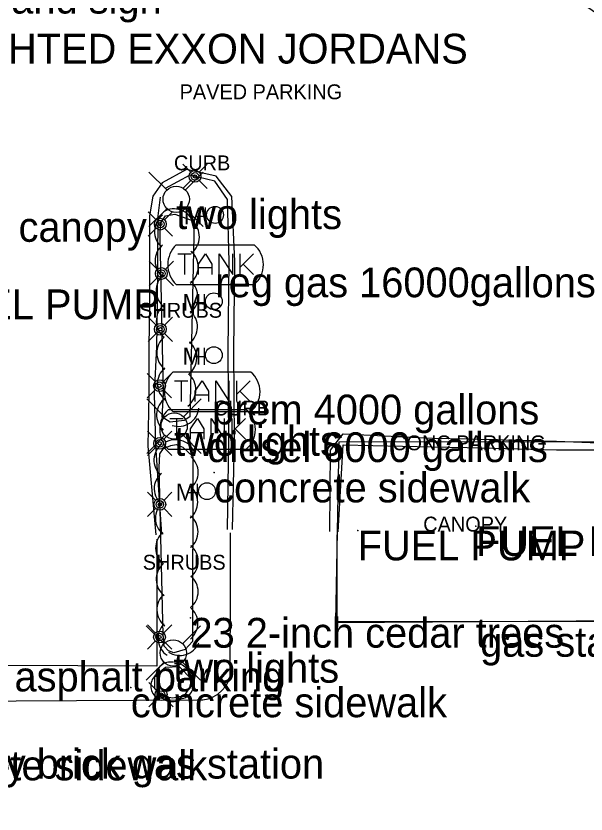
# Model space of a CAD drawing. Extents: x 1802180 to 1804859, y 572524 to 575172.
# Drawn here: x 1803809.7 to 1803905.5, y 573582.9 to 573717 of the extents above; entities that cross this region are included whole.
import ezdxf

# ---------------------------------------------------------------- set-up
doc = ezdxf.new("R2010")
doc.units = 0
for name, color, linetype in [('S_CURB', 7, 'Continuous'), ('S_CURB_ANNOT', 7, 'Continuous'), ('S_MANHOLE', 7, 'Continuous'), ('S_MISC_STRUCTURES', 7, 'Continuous'), ('S_MISC_STRUCTURES_ANNOT', 7, 'Continuous'), ('S_MSC_PT_SYM', 7, 'Continuous'), ('S_PARKING', 7, 'Continuous'), ('S_PARKING_ANNOT', 7, 'Continuous'), ('S_SIGN_ANNOT', 7, 'Continuous'), ('S_SPRINKLER_HEAD', 7, 'Continuous'), ('S_SURVEY_TEXT_ANNOT', 7, 'Continuous'), ('S_TANK', 7, 'Continuous'), ('S_TANK_ANNOT', 7, 'Continuous'), ('S_TREE', 7, 'Continuous'), ('S_TREE_ANNOT', 7, 'Continuous'), ('S_UTILITY_POLE', 7, 'Continuous'), ('S_UTILITY_POLE_ANNOT', 7, 'Continuous')]:
    doc.layers.add(name, color=color, linetype=linetype)

msp = doc.modelspace()

# ---------------------------------------------------------------- linework, layer by layer
at = {"layer": 'S_CURB'}
for points in [[(1803863.81, 573630.28), (1803864.63, 573644.9), (1803879.62, 573644.57), (1803885.5, 573644.45), (1803900.5, 573644.06), (1803911.39, 573644.06), (1803911.79, 573650.56), (1803912.2, 573665.52), (1803912.27, 573667.76), (1803912.6, 573680.35), (1803912.65, 573688), (1803912.94, 573697.46), (1803912.56, 573710.79), (1803911.72, 573714.98), (1803909.06, 573717.79)], [(1803845.21, 573630.66), (1803845.43, 573645.7), (1803845.32, 573660.7), (1803845.49, 573675.71), (1803845.24, 573686.14), (1803843.11, 573689.18), (1803838.87, 573690.18), (1803834.75, 573687.98)], [(1803833.89, 573686.51), (1803833.51, 573683.35), (1803833.39, 573668.33), (1803833.29, 573661.42), (1803832.91, 573653.45), (1803833.11, 573644.77), (1803834.12, 573629.91)]]:
    msp.add_lwpolyline(points, dxfattribs=at)
at = {"layer": 'S_MANHOLE'}
for p, q in [((1803841.53, 573681.91), (1803841.53, 573684.75)), ((1803839.95, 573683.32), (1803841.53, 573683.32)), ((1803841.32, 573667.39), (1803841.32, 573670.23)), ((1803839.74, 573668.8), (1803841.32, 573668.8)), ((1803841.34, 573658.35), (1803841.34, 573661.18)), ((1803839.76, 573659.75), (1803841.34, 573659.75)), ((1803840.19, 573635.5), (1803840.19, 573638.34)), ((1803838.61, 573636.91), (1803840.19, 573636.91))]:
    msp.add_line(p, q, dxfattribs=at)
for centre in [(1803843.12, 573683.53), (1803842.91, 573669.01), (1803842.92, 573659.96), (1803841.77, 573637.12)]:
    msp.add_circle(centre, 1.42, dxfattribs=at)
at = {"layer": 'S_MISC_STRUCTURES'}
msp.add_lwpolyline([(1803863.96, 573645.4), (1803912.16, 573645.46), (1803912.07, 573615.16), (1803863.43, 573615.23), (1803863.96, 573645.4)], dxfattribs=at)
at = {"layer": 'S_MSC_PT_SYM'}
for points in [[(1803842.97, 573640.23), (1803842.97, 573640.28), (1803842.97, 573640.23), (1803842.92, 573640.23), (1803842.97, 573640.23), (1803842.97, 573640.18), (1803842.97, 573640.23), (1803843.02, 573640.23)], [(1803886.97, 573631.23), (1803886.97, 573631.28), (1803886.97, 573631.23), (1803886.92, 573631.23), (1803886.97, 573631.23), (1803886.97, 573631.18), (1803886.97, 573631.23), (1803887.02, 573631.23)], [(1803867.1, 573630.49), (1803867.1, 573630.54), (1803867.1, 573630.49), (1803867.05, 573630.49), (1803867.1, 573630.49), (1803867.1, 573630.44), (1803867.1, 573630.49), (1803867.15, 573630.49)], [(1803838.99, 573615.82), (1803838.99, 573615.87), (1803838.99, 573615.82), (1803838.94, 573615.82), (1803838.99, 573615.82), (1803838.99, 573615.77), (1803838.99, 573615.82), (1803839.04, 573615.82)], [(1803887.67, 573614.3), (1803887.67, 573614.35), (1803887.67, 573614.3), (1803887.62, 573614.3), (1803887.67, 573614.3), (1803887.67, 573614.25), (1803887.67, 573614.3), (1803887.72, 573614.3)], [(1803828.96, 573604.13), (1803828.96, 573604.18), (1803828.96, 573604.13), (1803828.91, 573604.13), (1803828.96, 573604.13), (1803828.96, 573604.08), (1803828.96, 573604.13), (1803829.01, 573604.13)]]:
    msp.add_lwpolyline(points, dxfattribs=at)
at = {"layer": 'S_PARKING'}
for points in [[(1803862.4, 573630.36), (1803862.54, 573644.02), (1803864.67, 573646.75), (1803879.65, 573646.01), (1803885.53, 573645.89), (1803900.5, 573645.52), (1803910.44, 573645.12), (1803910.7, 573650.59), (1803911.05, 573665.56), (1803911.12, 573667.79), (1803911.39, 573680.35), (1803911.34, 573688.04), (1803911.64, 573697.42), (1803911.3, 573710.54), (1803910.73, 573714.03), (1803908.32, 573716.62), (1803904.69, 573719.08)], [(1803862.4, 573630.36), (1803862.54, 573644.02), (1803864.67, 573646.75), (1803879.65, 573646.01), (1803885.53, 573645.89), (1803900.5, 573645.52), (1803910.44, 573645.12), (1803910.7, 573650.59), (1803911.05, 573665.56), (1803911.12, 573667.79), (1803911.39, 573680.35), (1803911.34, 573688.04), (1803911.64, 573697.42), (1803911.3, 573710.54), (1803910.73, 573714.03), (1803908.32, 573716.62), (1803904.69, 573719.08)], [(1803846.03, 573630.65), (1803846.39, 573645.71), (1803846.27, 573660.69), (1803846.43, 573675.73), (1803845.94, 573686.63), (1803843.32, 573690.06), (1803838.34, 573691.15), (1803834.24, 573688.91), (1803832.66, 573686.65), (1803832.11, 573683.36), (1803832.12, 573668.35), (1803832.01, 573661.48), (1803832, 573653.42), (1803831.85, 573644.66), (1803833.17, 573629.77)], [(1803846.03, 573630.65), (1803846.39, 573645.71), (1803846.27, 573660.69), (1803846.43, 573675.73), (1803845.94, 573686.63), (1803843.32, 573690.06), (1803838.34, 573691.15), (1803834.24, 573688.91), (1803832.66, 573686.65)], [(1803832.66, 573686.65), (1803832.11, 573683.36), (1803832.12, 573668.35), (1803832.01, 573661.48), (1803832, 573653.42), (1803831.85, 573644.66), (1803833.17, 573629.77)], [(1803845.68, 573605.96), (1803845.68, 573605.96), (1803845.73, 573620.68), (1803845.73, 573630.14)], [(1803863.61, 573629.75), (1803863.58, 573615.07), (1803911.83, 573615.37)], [(1803833.33, 573629.06), (1803833.33, 573607.69), (1803713.66, 573608.23)], [(1803789.37, 573551.02), (1803789.36, 573601.75), (1803840.12, 573602.03)]]:
    msp.add_lwpolyline(points, dxfattribs=at)
msp.add_ellipse((1803840.4, 573607.53), major_axis=(5.34, -1.35), ratio=0.999645, start_param=4.909146, end_param=6.241468, dxfattribs=at)
at = {"layer": 'S_SPRINKLER_HEAD'}
for p, q in [((1803839.03, 573690.7), (1803837.69, 573692.05)), ((1803840.44, 573690.7), (1803841.78, 573692.05)), ((1803839.03, 573689.3), (1803837.69, 573687.96)), ((1803840.44, 573689.3), (1803841.78, 573687.96)), ((1803833.22, 573682.69), (1803831.87, 573684.03)), ((1803834.62, 573682.69), (1803835.97, 573684.03)), ((1803833.22, 573681.28), (1803831.87, 573679.94)), ((1803834.62, 573681.28), (1803835.97, 573679.94)), ((1803833.4, 573674.39), (1803832.06, 573675.73)), ((1803834.8, 573674.39), (1803836.15, 573675.73)), ((1803833.4, 573672.98), (1803832.06, 573671.64)), ((1803834.8, 573672.98), (1803836.15, 573671.64)), ((1803833.22, 573665.01), (1803831.88, 573666.36)), ((1803834.63, 573665.01), (1803835.97, 573666.36)), ((1803833.22, 573663.61), (1803831.88, 573662.27)), ((1803834.63, 573663.61), (1803835.97, 573662.27)), ((1803833.07, 573655.53), (1803831.73, 573656.88)), ((1803834.48, 573655.53), (1803835.82, 573656.88)), ((1803833.07, 573654.13), (1803831.73, 573652.79)), ((1803834.48, 573654.13), (1803835.82, 573652.79)), ((1803833.12, 573645.85), (1803831.78, 573647.19)), ((1803834.52, 573645.85), (1803835.87, 573647.19)), ((1803833.12, 573644.44), (1803831.78, 573643.1)), ((1803834.52, 573644.44), (1803835.87, 573643.1)), ((1803833.13, 573635.61), (1803831.79, 573636.95)), ((1803834.54, 573635.61), (1803835.88, 573636.95)), ((1803833.13, 573634.2), (1803831.79, 573632.86)), ((1803834.54, 573634.2), (1803835.88, 573632.86)), ((1803833.08, 573613.31), (1803831.74, 573614.65)), ((1803834.49, 573613.31), (1803835.83, 573614.65)), ((1803833.08, 573611.9), (1803831.74, 573610.56)), ((1803834.49, 573611.9), (1803835.83, 573610.56)), ((1803833.34, 573603.64), (1803832, 573604.99)), ((1803834.75, 573603.64), (1803836.09, 573604.99)), ((1803833.34, 573602.24), (1803832, 573600.9)), ((1803834.75, 573602.24), (1803836.09, 573600.9))]:
    msp.add_line(p, q, dxfattribs=at)
for centre, radius in [((1803839.74, 573690), 0.994), ((1803839.74, 573690), 0.634), ((1803839.74, 573690), 0.274), ((1803833.92, 573681.98), 0.994), ((1803833.92, 573681.98), 0.634), ((1803833.92, 573681.98), 0.274), ((1803834.1, 573673.68), 0.994), ((1803834.1, 573673.68), 0.634), ((1803834.1, 573673.68), 0.274), ((1803833.93, 573664.31), 0.994), ((1803833.93, 573664.31), 0.634), ((1803833.93, 573664.31), 0.274), ((1803833.78, 573654.83), 0.994), ((1803833.78, 573654.83), 0.634), ((1803833.78, 573654.83), 0.274), ((1803833.82, 573645.14), 0.994), ((1803833.82, 573645.14), 0.634), ((1803833.82, 573645.14), 0.274), ((1803833.84, 573634.9), 0.994), ((1803833.84, 573634.9), 0.634), ((1803833.84, 573634.9), 0.274), ((1803833.78, 573612.61), 0.994), ((1803833.78, 573612.61), 0.634), ((1803833.78, 573612.61), 0.274), ((1803834.05, 573602.94), 0.994), ((1803834.05, 573602.94), 0.634), ((1803834.05, 573602.94), 0.274)]:
    msp.add_circle(centre, radius, dxfattribs=at)
at = {"layer": 'S_TANK'}
for p, q in [((1803836.59, 573678.5), (1803849.7, 573678.5)), ((1803836.85, 573677.01), (1803839.11, 573677.01)), ((1803838.01, 573677.01), (1803838.01, 573673.52)), ((1803840.34, 573675.27), (1803841.5, 573677.01)), ((1803841.5, 573677.01), (1803842.6, 573675.27)), ((1803843.83, 573673.52), (1803843.83, 573677.01)), ((1803843.83, 573677.01), (1803846.09, 573673.52)), ((1803846.09, 573673.52), (1803846.09, 573677.01)), ((1803847.31, 573677.01), (1803847.31, 573673.52)), ((1803847.31, 573674.69), (1803849.57, 573677.01)), ((1803840.34, 573673.52), (1803840.34, 573675.27)), ((1803842.6, 573675.27), (1803842.6, 573673.52)), ((1803842.6, 573674.62), (1803840.34, 573674.62)), ((1803847.89, 573675.2), (1803849.57, 573673.52)), ((1803836.59, 573671.85), (1803849.7, 573671.85)), ((1803836.02, 573657.14), (1803849.13, 573657.14)), ((1803836.28, 573655.65), (1803838.54, 573655.65)), ((1803837.44, 573655.65), (1803837.44, 573652.17)), ((1803839.77, 573653.91), (1803840.93, 573655.65)), ((1803840.93, 573655.65), (1803842.03, 573653.91)), ((1803843.26, 573652.17), (1803843.26, 573655.65)), ((1803843.26, 573655.65), (1803845.52, 573652.17)), ((1803845.52, 573652.17), (1803845.52, 573655.65)), ((1803846.74, 573655.65), (1803846.74, 573652.17)), ((1803846.74, 573653.33), (1803849, 573655.65)), ((1803839.77, 573652.17), (1803839.77, 573653.91)), ((1803842.03, 573653.91), (1803842.03, 573652.17)), ((1803847.32, 573653.85), (1803849, 573652.17)), ((1803842.03, 573653.26), (1803839.77, 573653.26)), ((1803835.24, 573650.81), (1803848.35, 573650.81)), ((1803836.02, 573650.49), (1803849.13, 573650.49)), ((1803835.5, 573649.32), (1803837.76, 573649.32)), ((1803836.66, 573649.32), (1803836.66, 573645.84)), ((1803838.98, 573647.58), (1803840.15, 573649.32)), ((1803840.15, 573649.32), (1803841.24, 573647.58)), ((1803842.47, 573645.84), (1803842.47, 573649.32)), ((1803842.47, 573649.32), (1803844.73, 573645.84)), ((1803844.73, 573645.84), (1803844.73, 573649.32)), ((1803845.96, 573649.32), (1803845.96, 573645.84)), ((1803845.96, 573647), (1803848.22, 573649.32)), ((1803838.98, 573645.84), (1803838.98, 573647.58)), ((1803841.24, 573647.58), (1803841.24, 573645.84)), ((1803846.54, 573647.51), (1803848.22, 573645.84)), ((1803841.24, 573646.93), (1803838.98, 573646.93)), ((1803835.24, 573644.16), (1803848.35, 573644.16))]:
    msp.add_line(p, q, dxfattribs=at)
for centre, radius, start, end in [((1803839.77, 573675.17), 4.6, 133.7339, 226.2661), ((1803846.91, 573675.17), 4.34, 309.9965, 50.0035), ((1803839.2, 573653.81), 4.6, 133.7339, 226.2661), ((1803846.34, 573653.81), 4.34, 309.9965, 50.0035), ((1803838.42, 573647.48), 4.6, 133.7339, 226.2661), ((1803845.56, 573647.48), 4.34, 309.9965, 50.0035)]:
    msp.add_arc(centre, radius, start, end, dxfattribs=at)
at = {"layer": 'S_TREE'}
for points in [[(1803839.6, 573682.5), (1803838.86, 573649.59), (1803837.92, 573648.98), (1803835.59, 573648.71), (1803834.21, 573649.56), (1803834.44, 573653.44), (1803833.89, 573679.75), (1803833.96, 573682.12), (1803834.77, 573683.37), (1803836.36, 573683.68), (1803839.6, 573682.5)], [(1803839.37, 573642.92), (1803839.31, 573611.86), (1803838.07, 573610.52), (1803836.22, 573609.95), (1803835.27, 573610.29), (1803834.58, 573611.1), (1803834.39, 573612.99), (1803833.74, 573641.07), (1803833.86, 573643.36), (1803834.46, 573644.26), (1803835.7, 573644.79), (1803836.56, 573644.97), (1803837.73, 573644.5), (1803839.37, 573642.92)], [(1803839.18, 573605.53), (1803838.84, 573604.15), (1803837.94, 573602.73), (1803836.01, 573602.33), (1803834.37, 573602.62), (1803832.99, 573603.9), (1803833.02, 573606.1), (1803834.77, 573607.53), (1803837.1, 573607.63), (1803839.18, 573605.53)]]:
    msp.add_lwpolyline(points, dxfattribs=at)
for centre, radius, start, end in [((1803836.42, 573680.74), 3.47, 127.4743, 229.0712), ((1803836.22, 573681.07), 3.47, 19.0846, 120.6815), ((1803837.01, 573679.87), 3.47, 307.9074, 49.5043), ((1803836.51, 573675.82), 3.47, 130.4007, 231.9976), ((1803836.82, 573674.79), 3.47, 307.9074, 49.5043), ((1803836.68, 573670.79), 3.47, 130.4007, 231.9976), ((1803836.78, 573669.76), 3.47, 307.9074, 49.5043), ((1803836.72, 573665.71), 3.47, 130.4007, 231.9976), ((1803836.7, 573664.71), 3.47, 307.9074, 49.5043), ((1803836.8, 573660.34), 3.47, 130.4007, 231.9976), ((1803836.58, 573659.53), 3.47, 307.9074, 49.5043), ((1803836.91, 573655.16), 3.47, 130.4007, 231.9976), ((1803836.43, 573654.16), 3.47, 307.9074, 49.5043), ((1803836.77, 573649.91), 3.47, 125.7428, 227.3397), ((1803836.97, 573651.47), 3.47, 252.028, 353.6249), ((1803836.47, 573642.35), 3.42, 17.3905, 118.9874), ((1803836.27, 573642.33), 3.42, 126.3171, 227.914), ((1803836.87, 573640.27), 3.42, 309.08, 50.6769), ((1803836.32, 573637.54), 3.42, 130.5234, 232.1203), ((1803836.79, 573635.27), 3.42, 309.08, 50.6769), ((1803836.51, 573632.59), 3.42, 130.5234, 232.1203), ((1803836.85, 573630.31), 3.42, 309.08, 50.6769), ((1803836.55, 573627.58), 3.42, 130.5234, 232.1203), ((1803836.87, 573625.33), 3.42, 309.08, 50.6769), ((1803836.64, 573622.29), 3.42, 130.5234, 232.1203), ((1803836.86, 573620.23), 3.42, 309.08, 50.6769), ((1803836.76, 573617.18), 3.42, 130.5234, 232.1203), ((1803836.82, 573614.93), 3.42, 309.08, 50.6769), ((1803836.96, 573612.39), 3.42, 134.7513, 236.3482), ((1803837.2, 573612.94), 3.42, 236.3783, 337.9752), ((1803835.63, 573605.93), 2.48, 78.3867, 179.9836), ((1803836.55, 573605.64), 2.48, 353.9662, 95.5632), ((1803834.8, 573604.39), 2.48, 128.4335, 230.0304), ((1803837.04, 573604.69), 2.48, 277.0856, 18.6826), ((1803835.87, 573604.24), 2.48, 209.1194, 310.7163)]:
    msp.add_arc(centre, radius, start, end, dxfattribs=at)
at = {"layer": 'S_UTILITY_POLE'}
for p, q in [((1803834.99, 573687.73), (1803832.01, 573690.72)), ((1803838.17, 573687.73), (1803841.15, 573690.72)), ((1803834.99, 573684.55), (1803832.01, 573681.57)), ((1803838.17, 573684.55), (1803841.15, 573681.57)), ((1803834.65, 573649.63), (1803831.67, 573652.62)), ((1803837.83, 573649.63), (1803840.81, 573652.62)), ((1803834.65, 573646.46), (1803831.67, 573643.47)), ((1803837.83, 573646.46), (1803840.81, 573643.47)), ((1803834.5, 573611.52), (1803831.52, 573614.5)), ((1803837.68, 573611.52), (1803840.67, 573614.5)), ((1803834.5, 573608.34), (1803831.52, 573605.36)), ((1803837.68, 573608.34), (1803840.67, 573605.36))]:
    msp.add_line(p, q, dxfattribs=at)
for centre in [(1803836.59, 573686.15), (1803836.25, 573648.05), (1803836.1, 573609.94)]:
    msp.add_circle(centre, 2.21, dxfattribs=at)

# ---------------------------------------------------------------- texts
at = {"layer": 'S_CURB_ANNOT'}
for p in [(1803836.21, 573691.02), (1803842.86, 573649.83)]:
    msp.add_text('CURB', height=2.5, dxfattribs=at).set_placement(p)
at = {"layer": 'S_MANHOLE'}
for p in [(1803837.87, 573681.95), (1803837.66, 573667.43), (1803837.67, 573658.38), (1803836.52, 573635.54)]:
    msp.add_text('M', height=2.82, dxfattribs=at).set_placement(p)
at = {"layer": 'S_MISC_STRUCTURES_ANNOT'}
msp.add_text('CANOPY', height=2.5, dxfattribs=at).set_placement((1803878.11, 573630.33))
at = {"layer": 'S_PARKING_ANNOT'}
for s, p in [('PAVED PARKING', (1803837.17, 573702.96)), ('CONC PARKING', (1803872.89, 573643.98))]:
    msp.add_text(s, height=2.5, dxfattribs=at).set_placement(p)
at = {"layer": 'S_SIGN_ANNOT'}
msp.add_text('METAL/PLASTIC/LIGHTED EXXON JORDANS  ', height=5, dxfattribs=at).set_placement((1803743.67, 573708.96))
at = {"layer": 'S_SPRINKLER_HEAD'}
for p in [(1803839.69, 573689.95), (1803833.88, 573681.93), (1803834.06, 573673.63), (1803833.88, 573664.26), (1803833.73, 573654.78), (1803833.78, 573645.09), (1803833.79, 573634.85), (1803833.74, 573612.56), (1803834, 573602.89)]:
    msp.add_text('+', height=0.1, dxfattribs=at).set_placement(p)
at = {"layer": 'S_SURVEY_TEXT_ANNOT'}
for s, p in [('flower bedwith rocks and sign', (1803746.44, 573717.36)), ('gas station canopy', (1803775.9, 573679.01)), ('FUEL PUMP ', (1803795.59, 573666.01)), ('concrete sidewalk', (1803842.97, 573635.23)), ('FUEL PUMP ', (1803886.97, 573626.23)), ('FUEL PUMP ', (1803867.1, 573625.49)), ('23 2-inch cedar trees', (1803838.99, 573610.82)), ('gas station canopy', (1803887.67, 573609.3)), ('asphalt parking', (1803809.41, 573603.47)), ('concrete sidewalk', (1803828.96, 573599.13)), ('one story brick gas station', (1803783.79, 573588.83)), ('concrete sidewalk', (1803788.65, 573588.53))]:
    msp.add_text(s, height=5, dxfattribs=at).set_placement(p)
at = {"layer": 'S_TANK_ANNOT'}
for s, p in [('reg gas 16000gallons', (1803843.18, 573669.69)), ('prem 4000 gallons', (1803842.61, 573648.33)), ('diesel 6000 gallons', (1803841.82, 573642))]:
    msp.add_text(s, height=5, dxfattribs=at).set_placement(p)
at = {"layer": 'S_TREE_ANNOT'}
for p in [(1803830.37, 573666.25), (1803830.97, 573623.92)]:
    msp.add_text('SHRUBS', height=2.5, dxfattribs=at).set_placement(p)
at = {"layer": 'S_UTILITY_POLE_ANNOT'}
for p in [(1803836.59, 573681.15), (1803836.25, 573643.05), (1803836.1, 573604.94)]:
    msp.add_text('two lights', height=5, dxfattribs=at).set_placement(p)

doc.saveas('drawing.dxf')
